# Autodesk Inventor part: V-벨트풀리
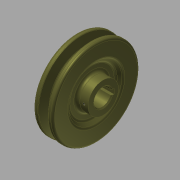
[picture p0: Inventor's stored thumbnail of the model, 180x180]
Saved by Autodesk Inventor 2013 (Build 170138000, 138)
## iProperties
Company: 한국ATC센터
Created: 2015-12
Part Number: V-벨트풀리
Document SubType Name: Modeling
Designer: mdu
Density: 7.25 g/cm^3
Mass: 594.58 g
Surface Area: 210.471 cm^2
Volume: 82.011 cm^3
Material: 주철
Author: mdu
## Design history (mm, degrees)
sketch "스케치1"
  geometry: L1 (-13, 0)-(13, 0); L2 (-13, 0)-(-13, 15); L3 (-13, 15)-(-9, 15); L4 (-9, 15)-(-9, 23); L5 (-9, 23)-(-13, 27); L6 (-13, 27)-(-13, 42.7); L7 (-13, 42.7)-(-8.325, 42.7); L8 (-8.325, 42.7)-(-5.574, 33.7); L9 (-5.574, 33.7)-(-1.426, 33.7); L10 (-1.426, 33.7)-(1.325, 42.7); L11 (1.325, 42.7)-(6, 42.7); L12 (6, 42.7)-(6, 27); L13 (6, 27)-(2, 23); L14 (2, 23)-(2, 15); L15 (2, 15)-(13, 15); L16 (13, 15)-(13, 0); L17 (-7.5, 40)-(0.5, 40); 2 further points
  constraints: 34 end point, 6 parallel, 5 collinear, 5 equal length, 4 perpendicular, 2 point on line, 1 coincident, 1 horizontal, 1 midpoint
  dimensions: "d0" = 26 distance of L1.start L1.end; "d1" = 2.7 distance between parallel lines of L7 L17; "d2" = 6.3 distance between parallel lines of L9 L17; "d3" = 8 distance of L17.start L17.end; "d4" = 34 deg angle of L10 L8; "d5" = 19 distance between parallel lines of L12 L6; "d7" = 30 diameter of L15 L1; "d8" = 46 diameter of L13.end L1; "d9" = 54 diameter of L12.end L1; "d10" = 4 distance between parallel lines of L2 L4; "d11" = 80 diameter of L17 L1
revolve "회전1" sketch "스케치1" stored, may be unused: angle "d12" = 90 deg
sketch "스케치2"
  geometry: L1 (-2.5, 8.124)-(-2.5, 10.8); L2 (-2.5, 10.8)-(2.5, 10.8); L3 (2.5, 10.8)-(2.5, 8.124); A1 r 8.5 centre (0, 0) between (-2.5, 8.124) and (2.5, 8.124); 1 further point
  constraints: 6 end point, 2 parallel, 2 point on circle, 1 centre point, 1 coincident, 1 perpendicular, 1 vertical
  dimensions: "d13" = 17 diameter of A1; "d14" = 19.3 dimension on A1 L2; "d15" = 5 distance of L1.end L2.end
extrude "돌출1" cut sketch "스케치2" stored distance "d16" = 10; taper "d17" = 0 deg
node "작업 평면1"
sketch "스케치3"
  geometry: L1 (-5.5, 15)-(-5.5, -15) reference; L2 (20.5, 27)-(20.5, -27) reference; 3 further points
  constraints: 1 horizontal alignment, 1 midpoint
  dimensions: "d18" = 4 distance from line of point (-1.5, 0) L1; "d33" = 22 distance from line of point (-1.5, 0) L2 (derived)
hole "구멍1" sketch "스케치3" at (-1.5, 0) diameter "d19" = 2.459; stored, may be unused: countersink angle "d23" = 90 deg, drill point angle "d25" = 118 deg; dims "d20" = 6, "d21" = 4, "d22" = 2, "d24" = 8
fillet "모깎기1" dims "d26" = 2, "d27" = 0.5, "d28" = 1, "d29" = 3
chamfer "모따기1" distance "d30" = 1; stored, may be unused: second distance "d31" = 2, angle "d32" = 45 deg
sketch "스케치4" dims "d35" = 70
  geometry: C1 r 2 at (35, 0); 2 further points
  constraints: 2 horizontal alignment, 1 centre point, 1 coincident, 2 other
  dimensions: "d34" = 4 diameter of C1
extrude "돌출2" cut sketch "스케치4" distance "d36" = 1; taper "d37" = 0 deg
fillet "모깎기3" dims "d40" = 0.5
node "솔리드1"
